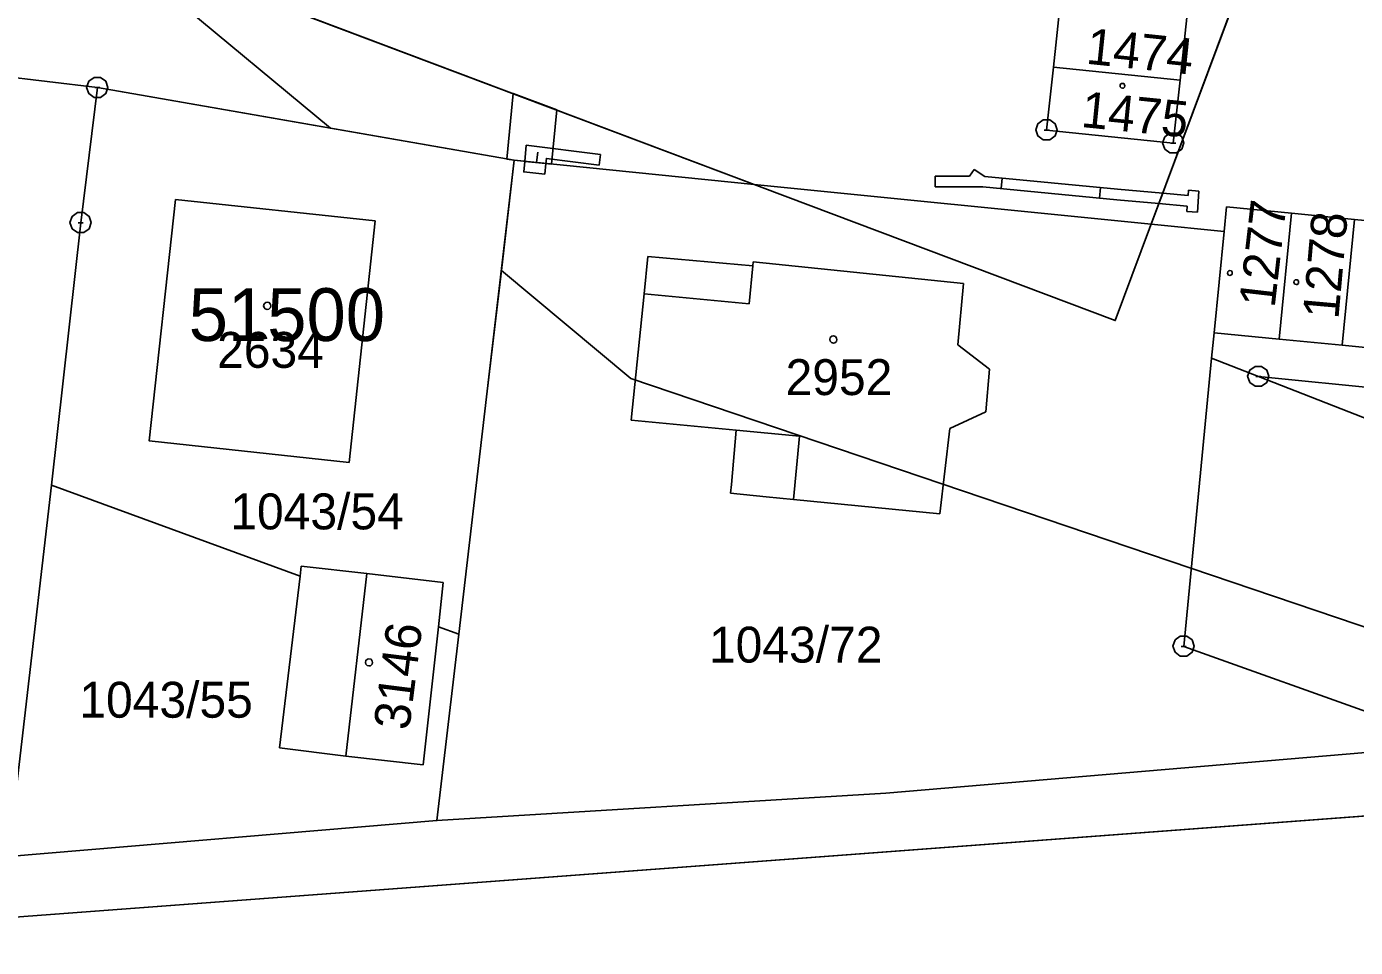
# Model space of a CAD drawing. Extents: x -777309 to -774195, y -1144706 to -1143600.
# Drawn here: x -775252.8 to -775189.8, y -1144461.3 to -1144417.7 of the extents above; entities that cross this region are included whole.
import ezdxf

# ---------------------------------------------------------------- set-up
doc = ezdxf.new("R2010")
doc.units = 0
for name, color, linetype in [('1', 7, 'Continuous'), ('11', 7, 'Continuous'), ('12', 7, 'Continuous'), ('13', 7, 'Continuous'), ('2', 7, 'Continuous'), ('4', 7, 'Continuous'), ('5', 7, 'Continuous'), ('8', 7, 'Continuous')]:
    doc.layers.add(name, color=color, linetype=linetype)

msp = doc.modelspace()

# ---------------------------------------------------------------- linework, layer by layer
at = {"layer": '1'}
for p, q in [((-775199.5, -1144427.02), (-775179.02, -1144372.13)), ((-775267.88, -1144406.43), (-775218.3, -1144425.13)), ((-775204.13, -1144419.58), (-775203.81, -1144416.6)), ((-775197.81, -1144417.22), (-775198.13, -1144420.2)), ((-775249.4, -1144420.55), (-775265.25, -1144418.62)), ((-775204.45, -1144422.56), (-775204.13, -1144419.58)), ((-775198.13, -1144420.2), (-775204.13, -1144419.58)), ((-775198.13, -1144420.2), (-775198.45, -1144423.18)), ((-775250.19, -1144426.95), (-775249.4, -1144420.55)), ((-775249.4, -1144420.55), (-775229.66, -1144423.99)), ((-775198.45, -1144423.18), (-775204.45, -1144422.56)), ((-775229.66, -1144423.99), (-775230.97, -1144435.19)), ((-775229.66, -1144423.99), (-775218.3, -1144425.13)), ((-775218.3, -1144425.13), (-775199.5, -1144427.02)), ((-775246.95, -1144437.27), (-775245.7, -1144425.84)), ((-775245.7, -1144425.84), (-775236.25, -1144426.86)), ((-775195.94, -1144426.19), (-775196.05, -1144427.37)), ((-775192.85, -1144426.49), (-775195.94, -1144426.19)), ((-775192.85, -1144426.49), (-775193.44, -1144432.46)), ((-775189.87, -1144426.79), (-775192.85, -1144426.49)), ((-775251.58, -1144439.37), (-775250.19, -1144426.95)), ((-775236.25, -1144426.86), (-775237.48, -1144438.3)), ((-775199.5, -1144427.02), (-775196.05, -1144427.37)), ((-775190.45, -1144432.75), (-775189.87, -1144426.79)), ((-775186.89, -1144427.09), (-775189.87, -1144426.79)), ((-775196.05, -1144427.37), (-775196.52, -1144432.16)), ((-775223.51, -1144430.32), (-775223.34, -1144428.54)), ((-775223.34, -1144428.54), (-775218.37, -1144428.99)), ((-775218.37, -1144428.99), (-775218.35, -1144428.8)), ((-775218.35, -1144428.8), (-775208.39, -1144429.82)), ((-775208.39, -1144429.82), (-775208.66, -1144432.73)), ((-775224.12, -1144436.3), (-775223.51, -1144430.32)), ((-775196.52, -1144432.16), (-775196.64, -1144433.36)), ((-775196.52, -1144432.16), (-775193.44, -1144432.46)), ((-775208.66, -1144432.73), (-775207.15, -1144433.88)), ((-775193.44, -1144432.46), (-775190.45, -1144432.75)), ((-775190.45, -1144432.75), (-775187.46, -1144433.05)), ((-775196.64, -1144433.36), (-775197.96, -1144447.01)), ((-775196.64, -1144433.36), (-775194.42, -1144434.23)), ((-775207.15, -1144433.88), (-775207.33, -1144435.91)), ((-775194.42, -1144434.23), (-775156.79, -1144437.99)), ((-775157.8, -1144448.55), (-775194.42, -1144434.23)), ((-775230.97, -1144435.19), (-775232.29, -1144446.43)), ((-775207.33, -1144435.91), (-775209.03, -1144436.7)), ((-775219.15, -1144436.77), (-775224.12, -1144436.3)), ((-775219.15, -1144436.77), (-775219.38, -1144439.34)), ((-775209.03, -1144436.7), (-775209.5, -1144440.74)), ((-775237.48, -1144438.3), (-775246.95, -1144437.27)), ((-775252.86, -1144450.42), (-775251.58, -1144439.37)), ((-775239.8, -1144443.68), (-775251.58, -1144439.37)), ((-775219.38, -1144439.34), (-775219.42, -1144439.76)), ((-775219.42, -1144439.76), (-775217.73, -1144439.93)), ((-775217.73, -1144439.93), (-775216.44, -1144440.06)), ((-775209.5, -1144440.74), (-775216.44, -1144440.06)), ((-775239.8, -1144443.68), (-775239.75, -1144443.21)), ((-775239.75, -1144443.21), (-775236.64, -1144443.56)), ((-775240.77, -1144451.81), (-775239.8, -1144443.68)), ((-775236.64, -1144443.56), (-775233.02, -1144443.98)), ((-775233.02, -1144443.98), (-775233.25, -1144446.08)), ((-775233.25, -1144446.08), (-775233.97, -1144452.63)), ((-775232.29, -1144446.43), (-775233.32, -1144455.26)), ((-775233.25, -1144446.08), (-775232.29, -1144446.43)), ((-775184.99, -1144451.66), (-775197.96, -1144447.01)), ((-775212.06, -1144453.97), (-775184.99, -1144451.66)), ((-775237.63, -1144452.21), (-775240.77, -1144451.81)), ((-775233.97, -1144452.63), (-775237.63, -1144452.21)), ((-775170.99, -1144453.66), (-775254.16, -1144459.9)), ((-775233.32, -1144455.26), (-775212.06, -1144453.97)), ((-775233.32, -1144455.26), (-775253.61, -1144456.96))]:
    msp.add_line(p, q, dxfattribs=at)
at = {"layer": '11'}
msp.add_line((-775249.17, -1144413.49), (-775238.37, -1144422.47), dxfattribs=at)
for points in [[(-775308.24, -1144339.37), (-775297.97, -1144340.23), (-775277.83, -1144342.65), (-775262.59, -1144344.6), (-775251.95, -1144346.82), (-775244.32, -1144348.69), (-775227.51, -1144352.79), (-775218.28, -1144355.05), (-775213.28, -1144356.23), (-775192.34, -1144361.18), (-775189.15, -1144361.13), (-775180.09, -1144362.23), (-775180.7, -1144372.14), (-775179.02, -1144372.13), (-775201.2, -1144431.58), (-775249.17, -1144413.49)], [(-775666.42, -1144398.43), (-775626.91, -1144413.11), (-775574.03, -1144428.55), (-775529.11, -1144439.07), (-775474.88, -1144449.28), (-775426.17, -1144455.72), (-775417.93, -1144456.81), (-775377.95, -1144459.1), (-775351.35, -1144460.68), (-775341.64, -1144460.83), (-775337.71, -1144460.89), (-775301.48, -1144461.27), (-775254.16, -1144459.9), (-775170.99, -1144453.66), (-775164.13, -1144452.88)], [(-775203.81, -1144416.6), (-775204.13, -1144419.58), (-775204.45, -1144422.56), (-775198.45, -1144423.18), (-775198.13, -1144420.2), (-775197.81, -1144417.22)], [(-775238.37, -1144422.47), (-775249.4, -1144420.55), (-775250.19, -1144426.95), (-775251.58, -1144439.37), (-775252.86, -1144450.42), (-775253.61, -1144456.96), (-775233.32, -1144455.26), (-775232.29, -1144446.43), (-775230.97, -1144435.19), (-775230.27, -1144429.21)], [(-775238.37, -1144422.47), (-775229.66, -1144423.99), (-775230.27, -1144429.21)], [(-775230.27, -1144429.21), (-775224.14, -1144434.32), (-775175.99, -1144450.63), (-775173.74, -1144451.39), (-775164.13, -1144452.88)]]:
    msp.add_lwpolyline(points, dxfattribs=at)
msp.add_lwpolyline([(-775245.7, -1144425.84), (-775236.25, -1144426.86), (-775237.48, -1144438.3), (-775246.95, -1144437.27)], close=True, dxfattribs=at)
at = {"layer": '12'}
for p, q in [((-775204.13, -1144419.58), (-775203.81, -1144416.6)), ((-775197.81, -1144417.22), (-775198.13, -1144420.2)), ((-775204.45, -1144422.56), (-775204.13, -1144419.58)), ((-775198.13, -1144420.2), (-775204.13, -1144419.58)), ((-775198.13, -1144420.2), (-775204.13, -1144419.58)), ((-775198.13, -1144420.2), (-775198.45, -1144423.18)), ((-775198.45, -1144423.18), (-775204.45, -1144422.56)), ((-775246.95, -1144437.27), (-775245.7, -1144425.84)), ((-775245.7, -1144425.84), (-775236.25, -1144426.86)), ((-775195.94, -1144426.19), (-775196.05, -1144427.37)), ((-775192.85, -1144426.49), (-775195.94, -1144426.19)), ((-775192.85, -1144426.49), (-775193.44, -1144432.46)), ((-775192.85, -1144426.49), (-775193.44, -1144432.46)), ((-775189.87, -1144426.79), (-775192.85, -1144426.49)), ((-775236.25, -1144426.86), (-775237.48, -1144438.3)), ((-775190.45, -1144432.75), (-775189.87, -1144426.79)), ((-775190.45, -1144432.75), (-775189.87, -1144426.79)), ((-775186.89, -1144427.09), (-775189.87, -1144426.79)), ((-775196.05, -1144427.37), (-775196.52, -1144432.16)), ((-775218.54, -1144430.79), (-775218.37, -1144428.99)), ((-775218.37, -1144428.99), (-775218.35, -1144428.8)), ((-775218.35, -1144428.8), (-775208.39, -1144429.82)), ((-775208.39, -1144429.82), (-775208.66, -1144432.73)), ((-775224.12, -1144436.3), (-775223.51, -1144430.32)), ((-775223.51, -1144430.32), (-775218.54, -1144430.79)), ((-775196.52, -1144432.16), (-775193.44, -1144432.46)), ((-775208.66, -1144432.73), (-775207.15, -1144433.88)), ((-775193.44, -1144432.46), (-775190.45, -1144432.75)), ((-775190.45, -1144432.75), (-775187.46, -1144433.05)), ((-775207.15, -1144433.88), (-775207.33, -1144435.91)), ((-775207.33, -1144435.91), (-775209.03, -1144436.7)), ((-775219.15, -1144436.77), (-775224.12, -1144436.3)), ((-775219.15, -1144436.77), (-775216.16, -1144437.06)), ((-775216.16, -1144437.06), (-775216.44, -1144440.06)), ((-775209.03, -1144436.7), (-775209.5, -1144440.74)), ((-775237.48, -1144438.3), (-775246.95, -1144437.27)), ((-775209.5, -1144440.74), (-775216.44, -1144440.06)), ((-775236.64, -1144443.56), (-775237.63, -1144452.21)), ((-775236.64, -1144443.56), (-775233.02, -1144443.98)), ((-775233.02, -1144443.98), (-775233.25, -1144446.08)), ((-775233.25, -1144446.08), (-775233.97, -1144452.63)), ((-775233.97, -1144452.63), (-775237.63, -1144452.21))]:
    msp.add_line(p, q, dxfattribs=at)
at = {"layer": '13'}
for p, q in [((-775230.02, -1144423.93), (-775229.71, -1144420.83)), ((-775229.71, -1144420.83), (-775227.65, -1144421.6)), ((-775227.65, -1144421.6), (-775227.9, -1144424.17)), ((-775229.66, -1144423.99), (-775230.02, -1144423.93)), ((-775227.9, -1144424.17), (-775229.66, -1144423.99)), ((-775228.601, -1144424.096), (-775228.551, -1144423.599)), ((-775208.1, -1144424.75), (-775207.88, -1144424.42)), ((-775207.88, -1144424.42), (-775207.37, -1144424.76)), ((-775209.73, -1144424.75), (-775208.1, -1144424.75)), ((-775209.73, -1144425.25), (-775209.73, -1144424.75)), ((-775207.37, -1144424.76), (-775201.09, -1144425.36)), ((-775206.605, -1144425.333), (-775206.557, -1144424.836)), ((-775207.47, -1144425.25), (-775209.73, -1144425.25)), ((-775201.13, -1144425.86), (-775207.47, -1144425.25)), ((-775201.895, -1144425.283), (-775201.942, -1144425.781)), ((-775199.13, -1144426.04), (-775201.13, -1144425.86)), ((-775201.09, -1144425.36), (-775198.95, -1144425.55)), ((-775199.13, -1144426.04), (-775198.95, -1144425.55)), ((-775198.95, -1144425.55), (-775199.13, -1144426.04)), ((-775198.95, -1144425.55), (-775197.75, -1144425.66)), ((-775197.75, -1144425.66), (-775197.73, -1144425.41)), ((-775197.73, -1144425.41), (-775197.24, -1144425.45)), ((-775197.24, -1144425.45), (-775197.31, -1144426.44)), ((-775197.79, -1144426.16), (-775199.13, -1144426.04)), ((-775197.81, -1144426.41), (-775197.79, -1144426.16)), ((-775197.31, -1144426.44), (-775197.81, -1144426.41))]:
    msp.add_line(p, q, dxfattribs=at)
for points in [[(-775229.16, -1144424.04), (-775229.09, -1144423.28), (-775225.58, -1144423.72), (-775225.64, -1144424.22), (-775228.14, -1144423.9), (-775228.17, -1144424.14)], [(-775228.17, -1144424.14), (-775228.22, -1144424.64), (-775229.21, -1144424.54), (-775229.16, -1144424.04)]]:
    msp.add_lwpolyline(points, close=True, dxfattribs=at)
at = {"layer": '4'}
for p, q in [((-775218.54, -1144430.79), (-775218.37, -1144428.99)), ((-775223.51, -1144430.32), (-775218.54, -1144430.79)), ((-775219.15, -1144436.77), (-775216.16, -1144437.06)), ((-775216.16, -1144437.06), (-775216.44, -1144440.06)), ((-775236.64, -1144443.56), (-775237.63, -1144452.21))]:
    msp.add_line(p, q, dxfattribs=at)
at = {"layer": '5'}
for points in [[(-775200.86, -1144420.346), (-775200.793, -1144420.36), (-775200.759, -1144420.42), (-775200.746, -1144420.46), (-775200.759, -1144420.52), (-775200.813, -1144420.567), (-775200.86, -1144420.574), (-775200.92, -1144420.554), (-775200.961, -1144420.514), (-775200.974, -1144420.46), (-775200.961, -1144420.4), (-775200.907, -1144420.353)], [(-775195.77, -1144429.216), (-775195.703, -1144429.23), (-775195.67, -1144429.29), (-775195.656, -1144429.33), (-775195.67, -1144429.39), (-775195.723, -1144429.437), (-775195.77, -1144429.444), (-775195.83, -1144429.424), (-775195.871, -1144429.384), (-775195.884, -1144429.33), (-775195.871, -1144429.27), (-775195.817, -1144429.223)], [(-775192.63, -1144429.646), (-775192.563, -1144429.66), (-775192.53, -1144429.72), (-775192.516, -1144429.76), (-775192.53, -1144429.82), (-775192.583, -1144429.867), (-775192.63, -1144429.874), (-775192.69, -1144429.854), (-775192.731, -1144429.814), (-775192.744, -1144429.76), (-775192.731, -1144429.7), (-775192.677, -1144429.653)], [(-775241.36, -1144430.71), (-775241.26, -1144430.73), (-775241.21, -1144430.82), (-775241.19, -1144430.88), (-775241.21, -1144430.97), (-775241.29, -1144431.04), (-775241.36, -1144431.05), (-775241.45, -1144431.02), (-775241.51, -1144430.96), (-775241.53, -1144430.88), (-775241.51, -1144430.79), (-775241.43, -1144430.72)], [(-775214.55, -1144432.31), (-775214.45, -1144432.33), (-775214.4, -1144432.42), (-775214.38, -1144432.48), (-775214.4, -1144432.57), (-775214.48, -1144432.64), (-775214.55, -1144432.65), (-775214.64, -1144432.62), (-775214.7, -1144432.56), (-775214.72, -1144432.48), (-775214.7, -1144432.39), (-775214.62, -1144432.32)], [(-775236.54, -1144447.6), (-775236.44, -1144447.62), (-775236.39, -1144447.71), (-775236.37, -1144447.77), (-775236.39, -1144447.86), (-775236.47, -1144447.93), (-775236.54, -1144447.94), (-775236.63, -1144447.91), (-775236.69, -1144447.85), (-775236.71, -1144447.77), (-775236.69, -1144447.68), (-775236.61, -1144447.61)]]:
    msp.add_lwpolyline(points, close=True, dxfattribs=at)
at = {"layer": '8'}
for p, q in [((-775249.52, -1144420.55), (-775249.28, -1144420.55)), ((-775204.57, -1144422.56), (-775204.33, -1144422.56)), ((-775198.57, -1144423.18), (-775198.33, -1144423.18)), ((-775250.31, -1144426.95), (-775250.07, -1144426.95)), ((-775194.54, -1144434.23), (-775194.3, -1144434.23)), ((-775198.08, -1144447.01), (-775197.84, -1144447.01))]:
    msp.add_line(p, q, dxfattribs=at)
for points in [[(-775249.25, -1144420.07), (-775249, -1144420.25), (-775248.9, -1144420.54), (-775249, -1144420.83), (-775249.25, -1144421.01), (-775249.56, -1144421.01), (-775249.81, -1144420.83), (-775249.91, -1144420.54), (-775249.81, -1144420.25), (-775249.56, -1144420.07)], [(-775204.3, -1144422.08), (-775204.05, -1144422.26), (-775203.95, -1144422.55), (-775204.05, -1144422.84), (-775204.3, -1144423.02), (-775204.61, -1144423.02), (-775204.86, -1144422.84), (-775204.96, -1144422.55), (-775204.86, -1144422.26), (-775204.61, -1144422.08)], [(-775198.3, -1144422.7), (-775198.05, -1144422.88), (-775197.95, -1144423.17), (-775198.05, -1144423.46), (-775198.3, -1144423.64), (-775198.61, -1144423.64), (-775198.86, -1144423.46), (-775198.96, -1144423.17), (-775198.86, -1144422.88), (-775198.61, -1144422.7)], [(-775250.04, -1144426.47), (-775249.79, -1144426.65), (-775249.69, -1144426.94), (-775249.79, -1144427.23), (-775250.04, -1144427.41), (-775250.35, -1144427.41), (-775250.6, -1144427.23), (-775250.7, -1144426.94), (-775250.6, -1144426.65), (-775250.35, -1144426.47)], [(-775194.27, -1144433.75), (-775194.02, -1144433.93), (-775193.92, -1144434.22), (-775194.02, -1144434.51), (-775194.27, -1144434.69), (-775194.58, -1144434.69), (-775194.83, -1144434.51), (-775194.93, -1144434.22), (-775194.83, -1144433.93), (-775194.58, -1144433.75)], [(-775197.81, -1144446.53), (-775197.56, -1144446.71), (-775197.46, -1144447), (-775197.56, -1144447.29), (-775197.81, -1144447.47), (-775198.12, -1144447.47), (-775198.37, -1144447.29), (-775198.47, -1144447), (-775198.37, -1144446.71), (-775198.12, -1144446.53)]]:
    msp.add_lwpolyline(points, close=True, dxfattribs=at)

# ---------------------------------------------------------------- texts
at = {"layer": '11'}
msp.add_text('51500', height=2.5, dxfattribs=at).set_placement((-775245.078, -1144432.55))
at = {"layer": '2'}
for s, rotation, p in [('1474', 354.03062, (-775202.619, -1144419.411)), ('1475', 354.2598, (-775202.859, -1144422.409)), ('1277', 83.42265, (-775193.655, -1144431.01)), ('1278', 84.91235, (-775190.635, -1144431.549)), ('3146', 82.7924, (-775234.639, -1144451.024))]:
    msp.add_text(s, height=1.7, rotation=rotation, dxfattribs=at).set_placement(p)
for s, p in [('2634', (-775243.733, -1144433.82)), ('2952', (-775216.813, -1144435.11)), ('1043/54', (-775243.107, -1144441.47)), ('1043/72', (-775220.441, -1144447.78)), ('1043/55', (-775250.257, -1144450.39))]:
    msp.add_text(s, height=1.7, dxfattribs=at).set_placement(p)

doc.saveas('drawing.dxf')
